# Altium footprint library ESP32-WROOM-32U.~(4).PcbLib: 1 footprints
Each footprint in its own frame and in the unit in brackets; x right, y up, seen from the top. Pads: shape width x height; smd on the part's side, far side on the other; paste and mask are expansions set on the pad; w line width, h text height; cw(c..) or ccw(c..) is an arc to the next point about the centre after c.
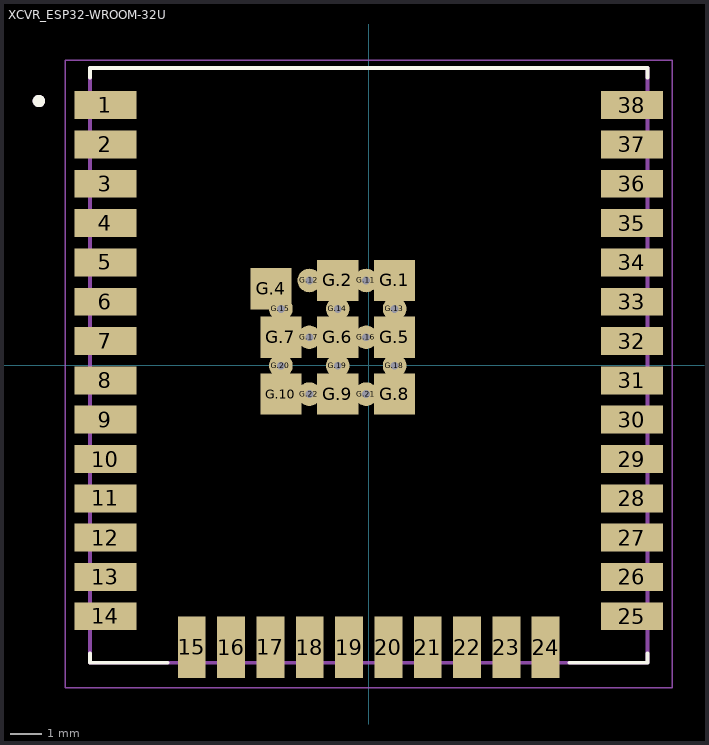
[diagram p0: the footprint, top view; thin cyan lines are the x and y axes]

## XCVR_ESP32-WROOM-32U [mm]
pads (59):
  rect 2x0.9 smd: 1(-8.5,8.41) 2(-8.5,7.14) 3(-8.5,5.87) 4(-8.5,4.6) 5(-8.5,3.33) 6(-8.5,2.06) 7(-8.5,0.79) 8(-8.5,-0.48) 9(-8.5,-1.75) 10(-8.5,-3.02) 11(-8.5,-4.29) 12(-8.5,-5.56) 13(-8.5,-6.83) 14(-8.5,-8.1) 25(8.5,-8.1) 26(8.5,-6.83) 27(8.5,-5.56) 28(8.5,-4.29) 29(8.5,-3.02) 30(8.5,-1.75) 31(8.5,-0.48) 32(8.5,0.79) 33(8.5,2.06) 34(8.5,3.33) 35(8.5,4.6) 36(8.5,5.87) 37(8.5,7.14) 38(8.5,8.41)
  rect 0.9x2 smd: 15(-5.715,-9.1) 16(-4.445,-9.1) 17(-3.175,-9.1) 18(-1.905,-9.1) 19(-0.635,-9.1) 20(0.635,-9.1) 21(1.905,-9.1) 22(3.175,-9.1) 23(4.445,-9.1) 24(5.715,-9.1)
  rect 1.33x1.33 smd: G.1(0.835,2.745) G.2(-1,2.745) G.4(-3.152,2.478) G.5(0.835,0.91) G.6(-1,0.91) G.7(-2.835,0.91) G.8(0.835,-0.925) G.9(-1,-0.925) G.10(-2.835,-0.925)
  round 0.762 hole 0.254: G.11(-0.082,2.745) G.12(-1.917,2.745) G.13(0.835,1.827) G.14(-1,1.827) G.15(-2.835,1.827) G.16(-0.082,0.91) G.17(-1.917,0.91) G.18(0.835,-0.008) G.19(-1,-0.008) G.20(-2.835,-0.008) G.21(-0.082,-0.925) G.22(-1.917,-0.925)
Top Overlay:
  circle w0.2: c-10.65,8.54 r0.1
  lines w0.127: -9,-9.3 -9,-9.6 -6.49,-9.6 ; -9,9.3 -9,9.6 9,9.6 9,9.3 ; 6.49,-9.6 9,-9.6 9,-9.3
Mechanical 13:
  circle w0.2: c-10.65,8.54 r0.1
  lines w0.127: -9,-9.6 -9,9.6 9,9.6 9,-9.6 -9,-9.6
Mechanical 15:
  lines w0.05: -9.8,-10.4 -9.8,9.85 9.8,9.85 9.8,-10.4 -9.8,-10.4
3D body "ESP32-WROOM-32U.STEP": height 3.3, standoff 0, extent -8.983,-9.561 9.017,9.639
